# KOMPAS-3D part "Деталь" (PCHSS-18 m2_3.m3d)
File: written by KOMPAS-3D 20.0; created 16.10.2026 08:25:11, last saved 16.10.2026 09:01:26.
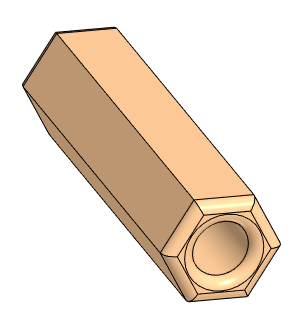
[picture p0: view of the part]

Document properties: Полное имя файла: D:\RicWork\Project-EPS32\box_compas\прочее\PCHSS-18 m2_3.m3d

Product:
- Part/product: Деталь
    Масса: 0.00185582

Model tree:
1. Эскиз:1
2. Элемент выдавливания:1
     Расстояние 1 = 17.8
3. Скругление:1  (with: Элемент выдавливания:1)
     Радиус = 0.5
